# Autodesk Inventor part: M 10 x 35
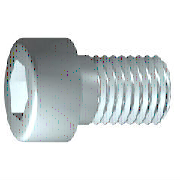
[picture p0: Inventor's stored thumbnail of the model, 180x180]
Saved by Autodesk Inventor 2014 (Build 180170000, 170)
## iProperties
Created: 2009-02
Part Number: M 10 x 35
Material: 강, 연강
Description: 6각머리 태핑 나사
Document SubType Name: Modeling
Standard: KS B 1003
Designer: KYOUNG IL JANG
Standards Organization: KS
Language: ko-KR
Size Designation: M 10 x 35
Categories: <MemberInstance><Categories><Category DisplayName="조임쇠" InternalName="e4da775c-781d-43d5-af7c-5136215cf5a6" Mnemonic="FSTN"><Category DisplayName="볼트" InternalN
Density: 7.86 g/cm^3
Appearance: 강철
Mass: 34.5961 g
Surface Area: 21.1658 cm^2
Volume: 4.40154 cm^3
IsCustomPart: 0
Author: KYOUNG IL JANG
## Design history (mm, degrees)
sketch "스케치1"
  geometry: L1 (-2.333, 0)-(35, 0); L2 (35, 0)-(35, 5); L3 (35, 5)-(3.75, 5); L4 (3.75, 5)-(2.83, 5); L5 (2.83, 5)-(0, 5); L6 (0, 5)-(0, 8); L7 (0, 8)-(-10, 8); L8 (-10, 8)-(-10, 4.619); L9 (-10, 4.619)-(-5, 4.619); L10 (-5, 4.619)-(-2.333, 0); L11 (-19, 0)-(44, 0) reference; L12 (0, -1.6)-(0, 9.6) reference; L13 (3.75, 5)-(0, 5)
  constraints: 22 end point, 6 parallel, 2 collinear, 2 perpendicular, 1 horizontal, 1 point on line
  dimensions: "d1" = 31.25 distance from line of L3.end L2 (= GEL); "d2" = 0.92028 distance of L4.end L3.end (computed from GAL); "d3" = 10 distance between parallel lines of L8 L6 (= KOH); "d4" = 5 distance of L8.end L9.end (= INTI); "d5" = 60 deg angle of L10 L1; "d6" = 10 diameter of L3 L1 (= GD); "d7" = 10 diameter of L5 L1 (= BDM); "d8" = 9.2376 diameter of L9 L1 (= 1.1547 x SW); "d9" = 16 diameter of L7 L1 (= KOD); "d26" = 35 distance between parallel lines of L12 L2 (= NLG)
revolve "본체" sketch "스케치1" stored, may be unused: angle "d10" = 90 deg
sketch "스케치2"
  geometry: L1 (0, -11.2)-(0, 11.2) reference; L2 (-11.2, 0)-(11.2, 0) reference; L3 (4.619, 0)-(2.309, -4); L4 (2.309, -4)-(-2.309, -4); L5 (-2.309, -4)-(-4.619, 0); L6 (-4.619, 0)-(-2.309, 4); L7 (-2.309, 4)-(2.309, 4); L8 (2.309, 4)-(4.619, 0); 2 further points
  constraints: 12 end point, 1 coincident, 1 horizontal alignment, 1 point on line, 12 other
extrude "슬롯" join sketch "스케치2" stored distance "d11" = 10; taper "d12" = 0 deg
workplane "Work Plane1"
fillet "Fillet2" dims "d30" = 0.1 (= R)
body "Solid1"
fillet "모깎기1" dims "d17" = 1 (= RR)
feature "스레드" dims "d13" = 31.25 (= GEL), "d14" = 0
chamfer "모따기1" distance "d15" = 0.92018 (= -0.5 x SPD + 0.5 x GD); stored, may be unused: second distance "d16" = 0.92018 (= GUL), angle "d27" = 45 deg
other parameters: "GD" = 10 (= NND) [user parameter; used in 2 equation terms], "NLG" = 35 [user parameter; used in 1 equation term], "GEL" = 31.25 [user parameter; used in 2 equation terms], "KOD" = 16 [user parameter; used in 1 equation term], "KOH" = 10 [user parameter; used in 1 equation term], "INTI" = 5 [user parameter; used in 1 equation term], "GAL" = 0.92018 (= 0.61345 x PTC) [user parameter; used in 1 equation term], "GUL" = 0.92018 (= 0.61345 x PTC) [user parameter; used in 1 equation term], "BDM" = 10 (= NND) [user parameter; used in 1 equation term], "SW" = 8 [user parameter; used in 2 equation terms], "RR" = 1 [user parameter; used in 1 equation term], "SPD" = 8.15965 (= NND - 1.2269 x PTC) [user parameter; used in 1 equation term], "d19" = 0, "d28" = 0, "d29" = 0, "R" = 0.1 [user parameter; used in 1 equation term], "PHH" = 0.4 [user parameter], "GD1" = 8.15965 (= THREADDIA - 1.2269 x PTC) [user parameter], "FAWI" = 45 deg [user parameter], "TPU" = 6.66667 (computed from PTC) [user parameter], "PTC" = 1.5 [user parameter; used in 5 equation terms], "TOA" = 30 deg [user parameter], "E0" = 9.24 (= 1.155 x SW) [user parameter]
